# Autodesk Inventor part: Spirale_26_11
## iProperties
Created: 2004-11
Part Number: Spirale_26_11
Cost Center: 1,778 kg
Material: S355 J2G3
Document SubType Name: Blech
Designer: ahuetter
Authority: 226194,67 mm^3
Manufacturer: Standard
Standards Organization: Custom
Author: ahuetter
SaveDate: 2004-11-25
SaveTime: 16:03
TotalMass: 1,778 kg
TotalVolume: 226194,67 mm^3
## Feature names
1. Spirale1
